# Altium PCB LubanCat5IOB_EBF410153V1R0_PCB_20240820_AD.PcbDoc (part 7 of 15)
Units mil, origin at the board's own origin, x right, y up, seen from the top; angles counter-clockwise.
Board outline 6811.02 x 4055.12 mil, 6 copper layers (TOP, GND02, ART03, ART04, PWR05, BOTTOM), stack 59.279 mil thick; 981 components, 783 nets, 3627 pads, 2669 vias.
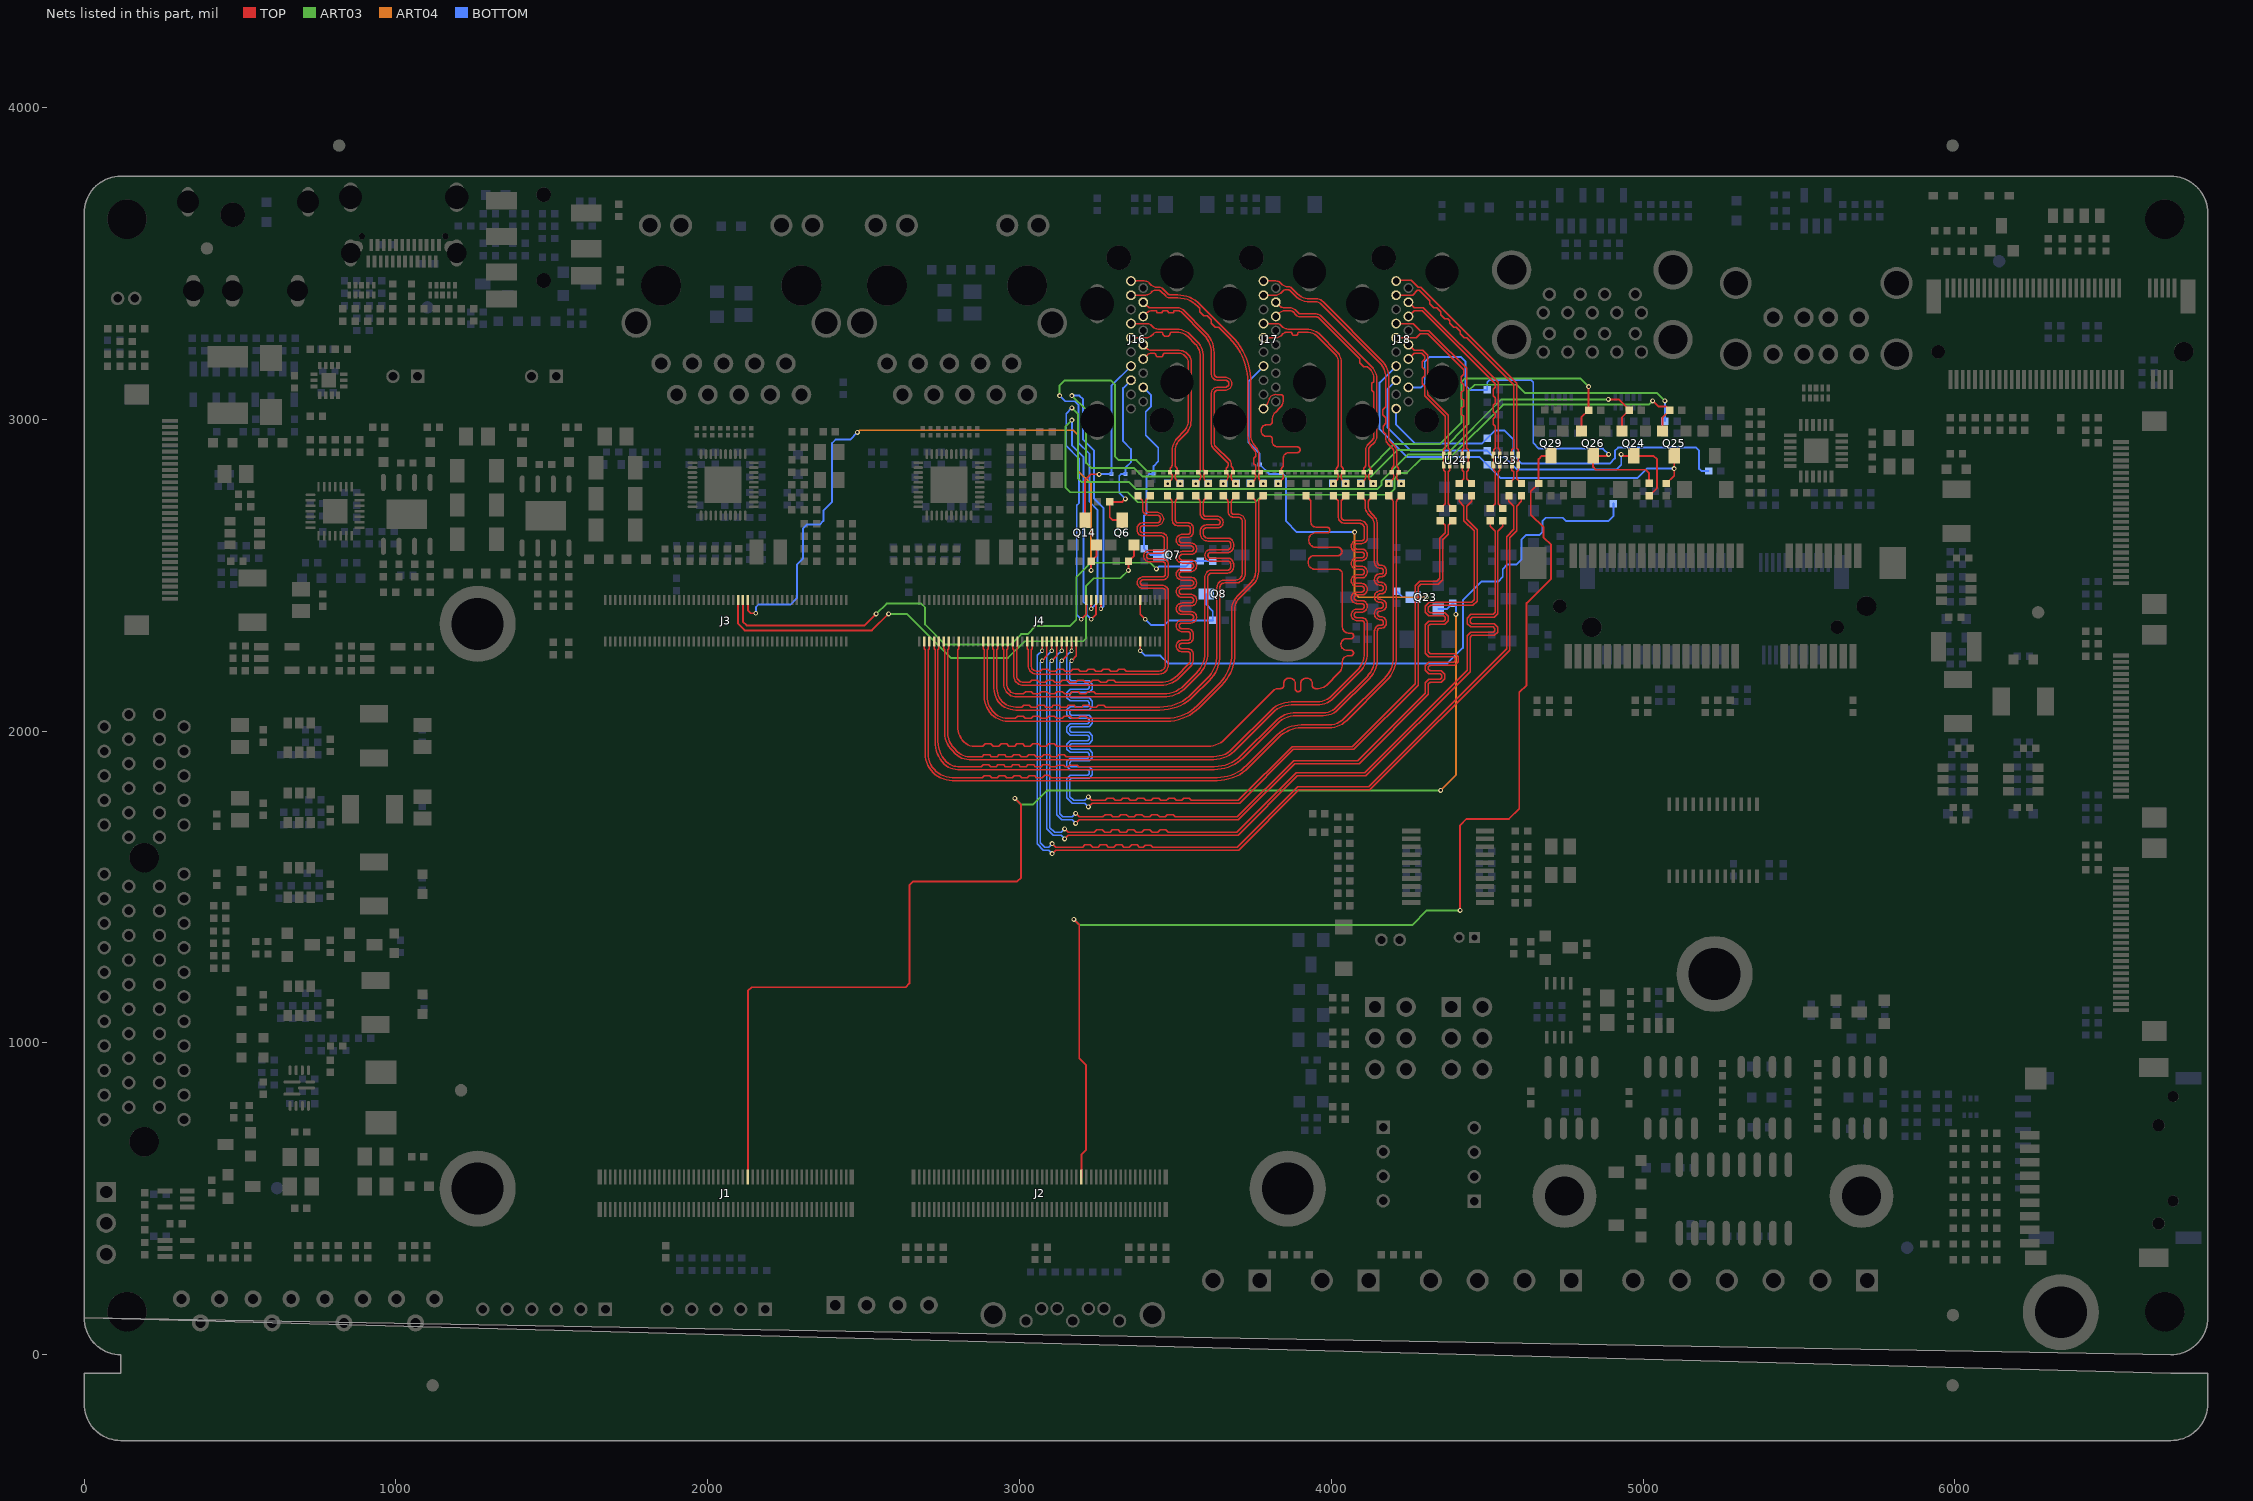
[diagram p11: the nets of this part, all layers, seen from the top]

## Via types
v1: diameter 16, hole 8, TOP to BOTTOM, 2357 vias
v2: diameter 14, hole 8, TOP to BOTTOM, 308 vias
v3: diameter 20, hole 10, TOP to BOTTOM, 4 vias

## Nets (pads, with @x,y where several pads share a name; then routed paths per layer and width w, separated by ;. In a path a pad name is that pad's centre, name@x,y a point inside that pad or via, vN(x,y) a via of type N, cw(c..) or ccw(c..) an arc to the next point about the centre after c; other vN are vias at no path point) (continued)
HDMI1_EARC-: C152.2 D34.2 J17.19 R180.2 | length 559.6
  TOP w4.5: J17.19@3782.91,3034.23 3784.53,3035.85 ccw(c3740.18,3080.21) 3800.54,3063.13 cw(c3822.28,3056.98) 3801,3064.57 3801,3064.73 cw(c3805.5,3064.72) 3801.75,3067.21 ccw(c3782.92,3079.7) 3802.43,3068.31 cw(c3821.95,3056.93) 3818.53,3079.26 ccw(c3815.03,3101.59) 3818.69,3079.29 cw(c3822.28,3056.98) 3825.87,3079.29 ccw(c3829.46,3101.6) 3829.46,3079 3837.5,3079 cw(c3837.5,3070) 3846.5,3070 3846.5,3063.8 cw(c3808.2,3063.8) 3835.28,3036.72 3821.77,3023.2 ccw(c3848.97,2996) 3810.5,2996 3810.5,2991.47 cw(c3801.5,2991.47) 3801.5,2982.47 3793.5,2982.47 ccw(c3793.5,2963.97) 3775,2963.97 3775,2963.22 ccw(c3792.75,2963.22) 3792.75,2945.47 3802.93,2945.47 cw(c3802.93,2937.9) 3810.5,2937.9 3810.5,2930.34 ccw(c3829.48,2930.34) 3829.48,2911.35 3891.5,2911.35 cw(c3891.5,2902.35) 3891.5,2893.35 3864.75,2893.35 ccw(c3864.75,2874.85) 3846.25,2874.85 3846.25,2852.6 cw(c3838.15,2852.6) 3843.88,2846.87 3842.72,2845.71 ccw(c3849.7,2838.73) 3839.83,2838.73 D34.2@3839.83,2830 3843.12,2826.71 cw(c3836.71,2820.3) 3845.77,2820.3 3845.77,2813.18 cw(c3837.67,2813.18) 3843.4,2807.45 v1(3830,2794.05)
HDMI1_TX_ON: J4.91 R190.1 | length 1971.7
  TOP w6: v2(3387.41,2258.14) J4.91@3387.41,2286.88
  BOTTOM w6: v2(3387.41,2258.14) 3403.55,2242 3452,2242 3477,2217 4372.63,2217 4422.2,2266.57 4422.2,2420.2 4481.37,2479.37 4535,2479.37 4550,2494.37 4550,2519.37 4565,2534.37 4595,2534.37 4610,2549.37 4610,2614.37 4625,2629.37 4668,2629.37 4678,2639.37 4678,2674.37 4688,2684.37 4743,2684.37 4754,2673.37 4889,2673.37 4905,2689.37 R190.1@4905,2729.69
HDMI_RX0N_PORT: J18.9 R206.2 U24.4 U24.7 | length 663.3
  TOP w4.5: J18.9@4208.11,3261.59 4208.46,3261.94 4272.31,3261.94 4284.75,3274.37 4309,3274.37 4324.75,3258.62 4324.9,3258.62 4424.5,3159.02 4424.5,3144.49 4417,3136.99 4417,3118.99 4424.5,3111.49 4424.5,3093.49 4417,3085.99 4417,3067.99 4424.5,3060.49 4424.5,3042.49 4417,3034.99 4417,3016.99 4424.5,3009.49 4424.5,2906.69 4419.69,2901.88 U24.7@4419.69,2885.12 U24.4@4419.69,2853.62 4419.69,2836.86 4424.78,2831.77 4424.78,2808.83 R206.2@4410,2794.05
HDMI_RX0P_PORT: J18.7 R205.2 U24.5 U24.6 | length 665.4
  TOP w4.5: J18.7@4208.11,3307.05 4208.19,3307.13 4262.24,3307.13 4285.5,3283.87 4312.94,3283.87 4328.69,3268.12 4328.84,3268.12 4434,3162.96 4434,2907.25 4439.37,2901.88 U24.6@4439.37,2885.12 U24.5@4439.37,2853.62 4439.37,2836.86 4434.28,2831.77 4434.28,2809.77 R205.2@4450,2794.05
HDMI_RX1N_PORT: J18.6 R204.2 U23.1 U23.10 | length 809.4
  TOP w4.5: J18.6@4247.48,3330.05 4265.48,3348.05 4291.88,3348.05 4525.5,3114.43 4525.5,3102.08 4519,3095.58 4519,3075.58 4525.5,3069.08 4525.5,3051.08 4519,3044.58 4519,3024.58 4525.5,3018.08 4525.5,3008.58 4519,3002.08 4519,2984.08 4525.5,2977.58 4525.5,2907.19 4520.63,2902.32 U23.10@4520.63,2885.12 U23.1@4520.63,2853.62 4520.63,2836.86 4525.72,2831.77 4525.72,2729.77 R204.2@4510,2714.05
HDMI_RX1P_PORT: J18.4 R203.2 U23.2 U23.9 | length 808.8
  TOP w4.5: J18.4@4247.48,3375.55 4265.48,3357.55 4295.82,3357.55 4535,3118.37 4535,2907.19 4540.31,2901.88 U23.9@4540.31,2885.12 U23.2@4540.31,2853.62 4540.31,2836.86 4535.22,2831.77 4535.22,2728.83 R203.2@4550,2714.05
HDMI_RX2N_PORT: J18.3 R202.2 U23.4 U23.7 | length 856.6
  TOP w4.5: J18.3@4208.11,3398 4208.27,3398.15 4260.78,3398.15 4275.99,3413.36 4282.57,3413.36 4315.23,3380.7 4315.23,3370.77 4327.96,3358.04 4337.89,3358.04 4350.62,3345.31 4350.62,3335.38 4363.35,3322.65 4373.28,3322.65 4380.01,3315.93 4380.01,3307.99 4392.73,3295.27 4400.67,3295.27 4413.4,3282.54 4413.4,3274.61 4426.12,3261.88 4434.06,3261.88 4584.78,3111.16 4584.78,2906.97 4579.69,2901.88 U23.7@4579.69,2885.12 U23.4@4579.69,2853.62 4579.69,2836.86 4584.78,2831.77 4584.78,2808.83 R202.2@4570,2794.05
HDMI_RX2P_PORT: J18.1 R201.2 U23.5 U23.6 | length 855.8
  TOP w4.5: J18.1@4208.11,3443.47 4210.01,3445.37 4256,3445.37 4278.51,3422.86 4286.51,3422.86 4594.28,3115.09 4594.28,2906.97 4599.37,2901.88 U23.6@4599.37,2885.12 U23.5@4599.37,2853.62 4599.37,2836.86 4594.28,2831.77 4594.28,2809.37 4609.6,2794.05 R201.2@4610,2794.05
HDMI_RX_CEC_M1: J4.74 Q25.2 R198.2 | length 3155.8
  TOP w6: v2(3229.93,2359) 3245.68,2374.75 J4.74@3245.68,2420.74 ; v1(5030.63,3059.37) 5048.63,3041.37 5073.32,3041.37 R198.2@5085.32,3029.37 5062.5,3006.55 Q25.2@5062.5,2962.87
  ART03 w6: v1(3168.02,2997.17) 3148,2977.15 3148,2781 3163,2766 3348,2766 3380,2734 3756,2734 3780,2758 4183,2758 4203,2778 4203,2811 4220,2828 4243,2828 4288,2873 4377,2873 4551,3047 5018.26,3047 v1(5030.63,3059.37)
  BOTTOM w6: v1(3168.02,2997.17) 3168.02,2916.98 3205,2880 3205,2415 3215.33,2404.67 3215.33,2373.6 v2(3229.93,2359)
HDMI_RX_CEC_PORT: D44.2 J18.13 Q25.3 R209.2 | length 1345.8
  TOP w6: R209.2@5075,2794.05 5100,2819.05 v1(5100,2841.77) Q25.3@5100,2882.87
  BOTTOM w6: J18.13@4208.11,3170.64 4155,3117.53 4155,2968 4244,2879 4475.69,2879 D44.2@4500.32,2854.37 4542.72,2811.97 4982.6,2811.97 5012.4,2841.77 v1(5100,2841.77)
HDMI_RX_CLKN: J4.65 R208.1 | length 3179.1
  TOP w4.5: v2(3166.94,2225.14) 3182.69,2240.89 J4.65@3182.69,2286.88 ; v1(3221,1788.83) 3231.33,1778.5 3275.58,1778.5 3278.83,1781.75 3282.08,1785 3300.08,1785 3303.32,1781.75 3306.57,1778.5 3324.57,1778.5 3327.82,1781.75 3331.07,1785 3349.07,1785 3352.32,1781.75 3355.57,1778.5 3373.57,1778.5 3376.82,1781.75 3380.07,1785 3398.07,1785 3401.32,1781.75 3404.57,1778.5 3422.57,1778.5 3425.82,1781.75 3429.06,1785 3447.06,1785 3450.31,1781.75 3453.56,1778.5 3471.56,1778.5 3474.81,1781.75 3478.06,1785 3496.06,1785 3499.31,1781.75 3502.56,1778.5 3520.56,1778.5 3523.81,1781.75 3527.06,1785 3545.06,1785 3548.3,1781.75 3551.55,1778.5 3702.5,1778.5 3874.5,1950.5 4068.06,1950.5 4269.28,2151.72 4269.28,2466.44 4283.85,2481 4338.56,2481 4347.5,2489.94 4347.5,2617.94 4365.25,2635.69 4365.25,2659.44 R208.1@4350,2674.69
  BOTTOM w4.5: v2(3166.94,2225.14) 3161,2219.2 3161,2166.41 3166.27,2161.14 3223.16,2161.14 3234,2150.3 3234,2134.98 3223.16,2124.14 3166.27,2124.14 3161,2118.87 3161,2111.41 3166.27,2106.14 3223.16,2106.14 3234,2095.3 3234,2079.98 3223.16,2069.14 3166.27,2069.14 3161,2063.87 3161,2056.41 3166.27,2051.14 3223.16,2051.14 3234,2040.31 3234,2024.98 3223.16,2014.14 3166.27,2014.14 3161,2008.87 3161,2001.41 3166.27,1996.14 3223.16,1996.14 3234,1985.31 3234,1969.98 3223.16,1959.14 3166.27,1959.14 3161,1953.87 3161,1946.41 3166.27,1941.14 3223.16,1941.14 3234,1930.31 3234,1914.98 3223.16,1904.14 3166.27,1904.14 3161,1898.87 3161,1891.41 3166.27,1886.14 3223.16,1886.14 3234,1875.31 3234,1859.98 3223.16,1849.14 3166.27,1849.14 3161,1843.87 3161,1790 3173.5,1777.5 3209.67,1777.5 v1(3221,1788.83)
HDMI_RX_CLKP: J4.63 R207.1 | length 3176.5
  TOP w4.5: v2(3166.94,2258.14) J4.63@3166.94,2286.88 ; v1(3221,1756.67) 3233.33,1769 3706.44,1769 3878.44,1941 4072,1941 4278.78,2147.78 4278.78,2462.5 4287.78,2471.5 4342.5,2471.5 4357,2486 4357,2614 4374.75,2631.75 4374.75,2659.44 R207.1@4390,2674.69
  BOTTOM w4.5: v2(3166.94,2258.14) 3151.5,2242.7 3151.5,2162.48 3162.34,2151.64 3219.23,2151.64 3224.5,2146.37 3224.5,2138.91 3219.23,2133.64 3162.34,2133.64 3151.5,2122.8 3151.5,2107.48 3162.34,2096.64 3219.23,2096.64 3224.5,2091.37 3224.5,2083.91 3219.23,2078.64 3162.34,2078.64 3151.5,2067.8 3151.5,2052.48 3162.34,2041.64 3219.23,2041.64 3224.5,2036.37 3224.5,2028.91 3219.23,2023.64 3162.34,2023.64 3151.5,2012.81 3151.5,1997.48 3162.34,1986.64 3219.23,1986.64 3224.5,1981.37 3224.5,1973.91 3219.23,1968.64 3162.34,1968.64 3151.5,1957.81 3151.5,1942.48 3162.34,1931.64 3219.23,1931.64 3224.5,1926.37 3224.5,1918.91 3219.23,1913.64 3162.34,1913.64 3151.5,1902.81 3151.5,1887.48 3162.34,1876.64 3219.23,1876.64 3224.5,1871.37 3224.5,1863.91 3219.23,1858.64 3162.34,1858.64 3151.5,1847.81 3151.5,1786.07 3169.57,1768 3209.67,1768 v1(3221,1756.67)
HDMI_RX_D0N: J4.61 R206.1 | length 3104
  TOP w4.5: v2(3135.44,2225.14) 3151.19,2240.89 J4.61@3151.19,2286.88 ; v1(3180,1736.33) 3191.33,1725 3267.73,1725 3274.73,1732 3292.73,1732 3299.73,1725 3317.73,1725 3324.73,1732 3342.73,1732 3349.73,1725 3367.73,1725 3374.73,1732 3392.73,1732 3399.73,1725 3417.73,1725 3424.73,1732 3442.73,1732 3449.73,1725 3467.73,1725 3474.73,1732 3492.73,1732 3499.73,1725 3698.56,1725 3879.06,1905.5 4085.5,1905.5 4302,2122 4302,2155.17 4312.84,2166.01 4349.23,2166.01 4354.5,2171.28 4354.5,2178.74 4349.23,2184.01 4312.84,2184.01 4302,2194.84 4302,2210.17 4312.84,2221.01 4392.23,2221.01 4397.5,2226.28 4397.5,2233.74 4392.23,2239.01 4312.84,2239.01 4302,2249.84 4302,2341.39 4312.84,2352.23 4360.23,2352.23 4365.5,2357.5 4365.5,2364.96 4360.23,2370.23 4312.84,2370.23 4302,2381.06 4302,2400.44 4314.56,2413 4450.56,2413 4458.5,2420.94 4458.5,2642.06 4425.25,2675.31 4425.25,2721.71 4410,2736.96 R206.1@4410,2754.69
  BOTTOM w4.5: v2(3135.44,2225.14) 3129.5,2219.2 3129.5,1734.94 3139.44,1725 3168.67,1725 v1(3180,1736.33)
HDMI_RX_D0P: J4.59 R205.1 | length 3103.9
  TOP w4.5: v2(3135.44,2258.14) J4.59@3135.44,2286.88 ; v1(3180,1704.17) 3191.33,1715.5 3702.5,1715.5 3883,1896 4089.44,1896 4311.5,2118.06 4311.5,2151.24 4316.77,2156.51 4353.16,2156.51 4364,2167.34 4364,2182.67 4353.16,2193.51 4316.77,2193.51 4311.5,2198.78 4311.5,2206.24 4316.77,2211.51 4396.16,2211.51 4407,2222.34 4407,2237.67 4396.16,2248.51 4316.77,2248.51 4311.5,2253.78 4311.5,2337.46 4316.77,2342.73 4364.16,2342.73 4375,2353.56 4375,2368.89 4364.16,2379.73 4316.77,2379.73 4311.5,2385 4311.5,2396.5 4318.5,2403.5 4454.5,2403.5 4468,2417 4468,2646 4434.75,2679.25 4434.75,2721.71 4450,2736.96 R205.1@4450,2754.69
  BOTTOM w4.5: v2(3135.44,2258.14) 3120,2242.7 3120,1731 3135.5,1715.5 3168.67,1715.5 v1(3180,1704.17)
HDMI_RX_D1N: J4.57 R204.1 | length 2928.6
  TOP w4.5: v2(3103.95,2225.14) 3119.7,2240.89 J4.57@3119.7,2286.88 ; v1(3145,1686.33) 3155.83,1675.5 3239.79,1675.5 3247.29,1683 3265.29,1683 3272.79,1675.5 3290.79,1675.5 3298.29,1683 3316.29,1683 3323.79,1675.5 3341.79,1675.5 3349.29,1683 3367.29,1683 3374.79,1675.5 3392.79,1675.5 3400.29,1683 3418.29,1683 3425.79,1675.5 3443.79,1675.5 3451.29,1683 3469.29,1683 3476.79,1675.5 3697.06,1675.5 3887.56,1866 4107,1866 4436,2195 4436,2305.39 4446.84,2316.23 4519.23,2316.23 4524.5,2321.5 4524.5,2328.96 4519.23,2334.23 4446.84,2334.23 4436,2345.06 4436,2362.44 4448.06,2374.5 4519.06,2374.5 4525.25,2380.69 4525.25,2641.71 4510,2656.96 R204.1@4510,2674.69
  BOTTOM w4.5: v2(3103.95,2225.14) 3097.5,2218.7 3097.5,1690.5 3113,1675 3133.67,1675 v1(3145,1686.33)
HDMI_RX_D1P: J4.55 R203.1 | length 2926.9
  TOP w4.5: v2(3103.95,2258.14) J4.55@3103.95,2286.88 ; v1(3145,1654.17) 3156.83,1666 3701,1666 3891.5,1856.5 4110.94,1856.5 4445.5,2191.06 4445.5,2301.46 4450.77,2306.73 4523.16,2306.73 4534,2317.56 4534,2332.89 4523.16,2343.73 4450.77,2343.73 4445.5,2349 4445.5,2358.5 4452,2365 4523,2365 4534.75,2376.75 4534.75,2641.71 4550,2656.96 R203.1@4550,2674.69
  BOTTOM w4.5: v2(3103.95,2258.14) 3088,2242.2 3088,1686.56 3109.07,1665.5 3133.67,1665.5 v1(3145,1654.17)
HDMI_RX_D2N: J4.53 R202.1 | length 2962.7
  TOP w4.5: v2(3072.45,2225.14) 3088.2,2240.89 J4.53@3088.2,2286.88 ; v1(3105,1639.33) 3116.33,1628 3202.75,1628 3209.75,1635 3227.75,1635 3234.75,1628 3252.75,1628 3259.75,1635 3277.75,1635 3284.75,1628 3302.75,1628 3309.75,1635 3327.75,1635 3334.75,1628 3352.75,1628 3359.75,1635 3377.75,1635 3384.75,1628 3396.81,1628 3402.81,1634 3420.81,1634 3426.81,1628 3699,1628 3892,1821 4119.56,1821 4562.5,2263.94 4562.5,2623.94 4585.25,2646.69 4585.25,2721.71 4570,2736.96 R202.1@4570,2754.69
  BOTTOM w4.5: v2(3072.45,2225.14) 3066.7,2219.39 3066.7,1642.24 3080.94,1628 3093.67,1628 v1(3105,1639.33)
HDMI_RX_D2P: J4.51 R201.1 | length 2963.4
  TOP w4.5: v2(3072.45,2258.14) J4.51@3072.45,2286.88 ; v1(3105,1607.17) 3116.33,1618.5 3702.94,1618.5 3895.94,1811.5 4123.5,1811.5 4572,2260 4572,2620 4594.75,2642.75 4594.75,2721.71 4610,2736.96 R201.1@4610,2754.69
  BOTTOM w4.5: v2(3072.45,2258.14) 3057.2,2242.89 3057.2,1638.3 3077.01,1618.5 3093.67,1618.5 v1(3105,1607.17)
HDMI_RX_DET: J2.67 Q29.3 R210.2 | length 3843.2
  TOP w6: v1(3174.81,1396) 3191.81,1379 3191.81,951 3213,929.81 3213,656 3198.43,641.43 J2.67@3198.43,569.96 ; v1(4413,1425) 4413,1698 4433,1718 4570,1718 4603,1751 4603,2124.37 4626.4,2147.77 4626.4,2410.6 4705,2489.2 4705,2597 4681.19,2620.82 4681.19,2653.18 4640,2694.37 4640,2769.05 R210.2@4665,2794.05 4665,2872.37 4675.5,2882.87 Q29.3@4705,2882.87
  ART03 w6: v1(3174.81,1396) 3192.81,1378 4260,1378 4307,1425 v1(4413,1425)
HDMI_RX_HPD_PORT: D41.2 J18.19 R214.2 | length 1270.8
  BOTTOM w6: J18.19@4208.11,3034.23 4208.11,2982.89 4269,2922 4482.95,2922 D41.2@4500.32,2939.37 4525.32,2964.37 4555,2964.37 4585,2934.37 4585,2884.37 4611.37,2858 4893.63,2858 4910,2874.37 4910,2899.37 4920,2909.37 5170,2909.37 5180,2899.37 5180,2841.17 5186.8,2834.37 R214.2@5210.32,2834.37
HDMI_RX_HPDOUT_M1: J4.76 R212.1 | length 3152.7
  TOP w6: v2(3261.43,2392) J4.76@3261.43,2420.74
  ART03 w6: v1(3168.02,3075.91) 3214,3029.93 3214,2860 3230,2844 3367,2844 3395,2816 4127,2816 4212,2901 4356,2901 4440,2985 4440,3091 4460,3111 4595,3111 4622,3084 5045.37,3084 v1(5070,3059.37)
  BOTTOM w6: v1(3168.02,3075.91) 3192.09,3075.91 3204,3064 3204,2935 3238.63,2900.37 3238.63,2746.37 3270,2715 3270,2400.57 v2(3261.43,2392) ; R212.1@5070,2994.05 v1(5070,3059.37)
HDMI_RX_SCL_M1: J4.70 Q24.2 R196.2 | length 3012.3
  TOP w6: v2(3198.43,2359) 3214.18,2374.75 J4.70@3214.18,2420.74 ; v1(4889,3064) 4921.37,3064 4955.32,3030.05 R196.2@4955.32,3029.37 4932.5,3006.55 Q24.2@4932.5,2962.87
  ART03 w6: v1(3168.02,3036.54) 3188,3016.56 3188,2810 3198.63,2799.37 3350.63,2799.37 3373,2777 4149,2777 4161,2789 4161,2802 4246,2887 4369,2887 4546,3064 v1(4889,3064)
  BOTTOM w6: v1(3168.02,3036.54) 3150,3018.52 3150,2915.2 3191,2874.2 3191,2731 3183.84,2723.84 3183.84,2373.6 v2(3198.43,2359)
HDMI_RX_SDA_M1: J4.72 Q26.2 R199.2 | length 3142.6
  TOP w6: v2(3229.93,2392) J4.72@3229.93,2420.74 ; Q26.2@4802.5,2962.87 4802.5,3006.55 R199.2@4825.32,3029.37 v1(4825.32,3105)
  ART03 w6: v1(3128.65,3075.91) 3128.65,3108.65 3145,3125 3293,3125 3306,3112 3306,2881 3318,2869 3375,2869 3410,2834 4115,2834 4202,2921 4349,2921 4418,2990 4418,3120 4429,3131 4799.32,3131 v1(4825.32,3105)
  BOTTOM w6: v1(3128.65,3075.91) 3146.56,3058 3177,3058 3189,3046 3189,2925 3224.63,2889.37 3224.63,2735.37 3250,2710 3250,2412.07 v2(3229.93,2392)
HDMI_RXCLKN_PORT: J18.12 R208.2 U24.1 U24.10 | length 602.9
  TOP w4.5: J18.12@4247.48,3193.52 4265.49,3211.52 4290.21,3211.52 4300,3201.74 4300,3192.24 4292,3184.24 4292,3166.24 4300,3158.24 4300,3140.24 4292,3132.24 4292,3114.24 4300,3106.24 4300,3074.9 4365.72,3009.18 4365.72,2906.97 4360.63,2901.88 U24.10@4360.63,2885.12 U24.1@4360.63,2853.62 4360.63,2836.86 4365.72,2831.77 4365.72,2729.77 R208.2@4350,2714.05
HDMI_RXCLKP_PORT: J18.10 R207.2 U24.2 U24.9 | length 605
  TOP w4.5: J18.10@4247.48,3239.03 4265.48,3221.02 4294.15,3221.02 4309.5,3205.67 4309.5,3078.84 4375.22,3013.12 4375.22,2906.97 4380.31,2901.88 U24.9@4380.31,2885.12 U24.2@4380.31,2853.62 4380.31,2836.86 4375.22,2831.77 4375.22,2728.83 R207.2@4390,2714.05
HDMI_RXDDC_SCL_PORT: D43.2 J18.15 Q24.3 R197.2 | length 1257.1
  TOP w6: v1(4930,2887.5) 4934.63,2882.87 Q24.3@4970,2882.87 5033.5,2882.87 5045,2871.37 5045,2779.69 R197.2@5019.68,2754.37
  BOTTOM w6: J18.15@4208.11,3125.16 4180,3097.05 4180,2974 4254.63,2899.37 D43.2@4500.32,2899.37 4521.52,2878.17 4556.2,2878.17 4595,2839.37 4915,2839.37 4930,2854.37 v1(4930,2887.5)
HDMI_RXDDC_SDA_PORT: D42.2 J18.16 Q26.3 R200.2 | length 1359.8
  TOP w6: v1(4890,2887.5) 4885.37,2882.87 Q26.3@4840,2882.87 4840,2847.37 4849,2838.37 5008,2838.37 5019.68,2826.69 R200.2@5019.68,2794.37
  BOTTOM w6: J18.16@4247.48,3102.49 4288.2,3102.49 4300,3114.29 4300,3184.37 4315,3199.37 4416.2,3199.37 4431,3184.57 4431,3108.37 4445,3094.37 D42.2@4500.32,3094.37 4500.32,3118.37 4508.32,3126.37 4640.03,3126.37 4648.03,3118.37 4648.03,2924.23 4666.2,2906.06 4871.44,2906.06 v1(4890,2887.5)
HDMI_TX0_CEC_M0: J3.60 Q14.2 R170.2 | length 2146
  TOP w6: J3.60@2128.84,2420.74 2128.84,2388 2138.84,2378 v2(2154.52,2378) ; v1(3229.68,2515.68) R170.2@3229.68,2545 3247.5,2562.82 Q14.2@3247.5,2596.5
  ART04 w6: v1(2480.1,2957.8) 2487.3,2965 3172.7,2965 3187,2950.7 3187,2835.71 3229.68,2793.03 v1(3229.68,2515.68)
  BOTTOM w6: v2(2154.52,2378) 2154.52,2397.52 2163,2406 2266,2406 2286,2426 2286,2534 2306,2554 2306,2650 2318,2662 2359,2662 2371,2674 2371,2707 2399,2735 2399,2924 2410,2935 2457.3,2935 v1(2480.1,2957.8)
HDMI_TX0_CEC_PORT: D31.2 J16.13 Q14.3 | length 593.7
  TOP w6: Q14.3@3210,2676.5 3210,2805 3228.74,2823.74 v1(3255.63,2823.74)
  BOTTOM w6: v1(3255.63,2823.74) 3256.45,2824.56 D31.2@3295,2824.56 3295,3107.92 J16.13@3357.72,3170.64
HDMI_TX0_D0N: C136.1 J4.37 | length 1792.2
  TOP w4.5: J4.37@2962.22,2286.88 2962.22,2263.82 2959.09,2260.7 2959.09,2151.89 ccw(c2991.98,2151.89) 2991.98,2119 3012.9,2119 3019.9,2126 3037.9,2126 3044.9,2119 3062.9,2119 3069.9,2126 3087.9,2126 3094.9,2119 3112.9,2119 3119.9,2126 3137.9,2126 3144.9,2119 3162.9,2119 3169.9,2126 3187.9,2126 3194.9,2119 3212.9,2119 3219.9,2126 3237.9,2126 3244.9,2119 3461.54,2119 ccw(c3461.54,2213.2) 3528.16,2146.59 3567.26,2185.7 ccw(c3501.51,2251.45) 3594.5,2251.45 3594.5,2492.74 cw(c3618.26,2492.74) 3618.26,2516.5 3668,2516.5 ccw(c3668,2525.5) 3677,2525.5 3677,2536 ccw(c3668,2536) 3668,2545 3613.5,2545 cw(c3613.5,2563.5) 3613.5,2582 3668,2582 ccw(c3668,2591) 3677,2591 3677,2600.5 ccw(c3668,2600.5) 3668,2609.5 3603.77,2609.5 cw(c3603.77,2633.02) 3580.25,2633.02 3580.25,2642.52 cw(c3598.75,2642.52) 3598.75,2661.02 3634.5,2661.02 ccw(c3634.5,2670.02) 3634.5,2679.02 3598.75,2679.02 cw(c3598.75,2697.52) 3580.25,2697.52 3580.25,2733 ccw(c3564.7,2733) 3575.7,2743.99 C136.1@3565,2754.69
HDMI_TX0_D0N_PORT: C136.2 D50.2 J16.9 R167.1 | length 703.3
  TOP w4.5: J16.9@3357.72,3261.59 3374.49,3261.59 3374.53,3261.62 3407.43,3261.62 ; 3407.43,3261.63 ccw(c3407.43,3284.13) 3423.35,3268.22 3428.41,3273.28 cw(c3444.32,3257.37) 3444.32,3279.87 3453.82,3279.87 cw(c3453.82,3273.43) 3460.26,3273.43 ccw(c3466.69,3273.43) 3466.69,3267 3476.32,3267 ccw(c3476.32,3273.43) 3482.76,3273.43 cw(c3489.19,3273.43) 3489.19,3279.87 3504.52,3279.87 cw(c3504.52,3228.75) 3540.67,3264.9 3562.69,3242.88 ; 3562.69,3242.87 cw(c3519.69,3199.88) 3580.5,3199.88 3580.5,2840.94 cw(c3570.2,2840.94) 3577.48,2833.65 D50.2@3573.83,2830 3577.98,2825.85 cw(c3569.49,2817.36) 3581.5,2817.36 3581.5,2815.99 cw(c3568.37,2815.99) 3577.65,2806.7 v1(3565,2794.05)
HDMI_TX0_D0P: C135.1 J4.35 | length 1793.1
  TOP w4.5: J4.35@2946.47,2286.88 2946.47,2263.82 2949.59,2260.7 2949.59,2151.89 ccw(c2991.98,2151.89) 2991.98,2109.5 3461.54,2109.5 ccw(c3461.54,2213.2) 3534.87,2139.87 3573.98,2178.98 ccw(c3501.51,2251.45) 3604,2251.45 3604,2492.74 cw(c3618.26,2492.74) 3618.26,2507 3668,2507 ccw(c3668,2525.5) 3686.5,2525.5 3686.5,2536 ccw(c3668,2536) 3668,2554.5 3613.5,2554.5 cw(c3613.5,2563.5) 3613.5,2572.5 3668,2572.5 ccw(c3668,2591) 3686.5,2591 3686.5,2600.5 ccw(c3668,2600.5) 3668,2619 3603.77,2619 cw(c3603.77,2633.02) 3589.75,2633.02 3589.75,2642.52 cw(c3598.75,2642.52) 3598.75,2651.52 3634.5,2651.52 ccw(c3634.5,2670.02) 3634.5,2688.52 3598.75,2688.52 cw(c3598.75,2697.52) 3589.75,2697.52 3589.75,2733 cw(c3605.3,2733) 3594.3,2743.99 C135.1@3605,2754.69
HDMI_TX0_D0P_PORT: C135.2 D51.2 J16.7 R168.1 | length 701.7
  TOP w4.5: J16.7@3357.72,3307.05 3374.49,3307.05 3374.57,3307.13 3407.92,3307.13 cw(c3407.92,3284.63) 3423.83,3300.54 3428.41,3295.96 ccw(c3444.32,3311.87) 3444.32,3289.37 3504.52,3289.37 cw(c3504.52,3228.75) 3547.38,3271.62 3569.41,3249.59 cw(c3519.69,3199.88) 3590,3199.88 3590,2841.79 ccw(c3601.15,2841.79) 3593.27,2833.9 D51.2@3597.17,2830 3593.77,2826.6 ccw(c3600.45,2819.92) 3591,2819.92 3591,2815.49 ccw(c3608.96,2815.49) 3596.26,2802.79 v1(3605,2794.05)
HDMI_TX0_D1N: C134.1 J4.33 | length 1614.6
  TOP w4.5: J4.33@2930.72,2286.88 2930.72,2263.82 2927.59,2260.7 2927.59,2137.35 ccw(c2987.94,2137.35) 2945.27,2094.68 ccw(c2987.94,2137.34) 2987.94,2077 3007.03,2077 3013.03,2083 3031.03,2083 3037.03,2077 3055.03,2077 3061.03,2083 3079.03,2083 3085.03,2077 3103.03,2077 3109.03,2083 3127.03,2083 3133.03,2077 3151.03,2077 3157.03,2083 3175.03,2083 3181.03,2077 3199.03,2077 3205.03,2083 3223.03,2083 3229.03,2077 3247.03,2077 3253.03,2083 3271.03,2083 3277.03,2077 3450.71,2077 ccw(c3450.71,2221.51) 3552.89,2119.33 3601.33,2167.76 ccw(c3523.65,2245.44) 3633.5,2245.43 3633.5,2460.26 cw(c3657.74,2460.26) 3657.74,2484.5 3693.31,2484.5 ccw(c3693.31,2505.69) 3714.5,2505.69 3714.5,2672.74 ccw(c3701.49,2672.74) 3701.49,2685.75 3687.75,2685.75 cw(c3687.75,2704.25) 3669.25,2704.25 3669.25,2733 ccw(c3653.7,2733) 3664.7,2743.99 C134.1@3654,2754.69
HDMI_TX0_D1N_PORT: C134.2 D52.2 J16.6 R165.1 | length 847.7
  TOP w4.5: J16.6@3397.09,3330.05 3408.98,3341.94 cw(c3423.73,3327.2) 3423.73,3348.05 3437.07,3348.05 cw(c3437.07,3344.53) 3440.59,3344.53 ; 3440.59,3344.53 ccw(c3444.12,3344.53) 3444.12,3341 3455.07,3341 ccw(c3455.07,3344.53) 3458.59,3344.53 ; 3458.59,3344.53 cw(c3462.12,3344.53) 3462.12,3348.05 3473.07,3348.05 cw(c3473.07,3344.53) 3476.59,3344.53 ; 3476.59,3344.53 ccw(c3480.12,3344.53) 3480.12,3341 3491.07,3341 ccw(c3491.07,3344.53) 3494.59,3344.53 ; 3494.59,3344.53 cw(c3498.12,3344.53) 3498.12,3348.05 3508.93,3348.05 cw(c3508.93,3335.05) 3518.13,3344.24 3590.97,3271.4 cw(c3532.96,3213.39) 3615,3213.39 3615,3146.12 ccw(c3635.75,3146.12) 3635.75,3125.37 3660.25,3125.37 cw(c3660.25,3114.12) 3660.25,3102.87 3635.75,3102.87 ccw(c3635.75,3082.12) 3615,3082.12 3615,2923.32 ccw(c3637.5,2923.32) 3621.59,2907.41 3667.12,2861.88 cw(c3661.99,2856.74) 3669.25,2856.74 3669.25,2853.33 cw(c3659.38,2853.33) 3666.36,2846.35 3665.72,2845.71 ccw(c3672.7,2838.73) 3662.83,2838.73 D52.2@3662.83,2830 3666.23,2826.6 cw(c3659.55,2819.92) 3669,2819.92 3669,2815.99 cw(c3652.24,2815.99) 3664.09,2804.14 v1(3654,2794.05)
HDMI_TX0_D1P: C133.1 J4.31 | length 1614.6
  TOP w4.5: J4.31@2914.97,2286.88 2914.97,2263.82 2918.09,2260.7 2918.09,2137.35 ccw(c2987.94,2137.35) 2938.55,2087.96 ccw(c2987.94,2137.34) 2987.94,2067.5 3450.71,2067.5 ccw(c3450.71,2221.51) 3559.61,2112.61 3608.04,2161.04 ccw(c3523.65,2245.43) 3643,2245.43 3643,2460.26 cw(c3657.74,2460.26) 3657.74,2475 3693.31,2475 ccw(c3693.31,2505.69) 3724,2505.69 3724,2672.74 ccw(c3701.49,2672.74) 3701.49,2695.25 3687.75,2695.25 cw(c3687.75,2704.25) 3678.75,2704.25 3678.75,2733 cw(c3694.3,2733) 3683.3,2743.99 C133.1@3694,2754.69
HDMI_TX0_D1P_PORT: C133.2 D53.2 J16.4 R166.1 | length 847.1
  TOP w4.5: J16.4@3397.09,3375.55 3410.41,3362.24 ccw(c3421.71,3373.54) 3421.71,3357.55 3508.93,3357.55 cw(c3508.93,3335.05) 3524.85,3350.96 3597.69,3278.12 cw(c3532.95,3213.39) 3624.5,3213.39 3624.5,3146.12 ccw(c3635.75,3146.12) 3635.75,3134.87 3660.25,3134.87 cw(c3660.25,3114.12) 3660.25,3093.37 3635.75,3093.37 ccw(c3635.75,3082.12) 3624.5,3082.12 3624.5,2923.32 ccw(c3637.5,2923.32) 3628.31,2914.13 3673.84,2868.59 cw(c3661.99,2856.74) 3678.75,2856.74 3678.75,2853.33 ccw(c3688.62,2853.33) 3681.64,2846.35 3682.28,2845.71 cw(c3675.3,2838.73) 3685.17,2838.73 D53.2@3685.17,2830 3681.52,2826.35 ccw(c3688.8,2819.06) 3678.5,2819.06 3678.5,2815.99 ccw(c3694.05,2815.99) 3683.05,2805 v1(3694,2794.05)
HDMI_TX0_D2N: C132.1 J4.29 | length 1677.1
  TOP w4.5: J4.29@2899.22,2286.88 2899.22,2263.82 2896.1,2260.7 2896.1,2112.28 ccw(c2970.38,2112.28) 2917.86,2059.76 ccw(c2963.14,2105.04) 2963.14,2041 2987.22,2041 2994.22,2048 3012.22,2048 3019.22,2041 3037.22,2041 3044.22,2048 3062.22,2048 3069.22,2041 3087.22,2041 3094.22,2048 3112.22,2048 3119.22,2041 3137.22,2041 3144.22,2048 3162.22,2048 3169.22,2041 3187.22,2041 3194.22,2048 3212.22,2048 3219.22,2041 3471.72,2041 ccw(c3471.72,2179.29) 3569.51,2081.51 3642.04,2154.04 ccw(c3547.98,2248.1) 3681,2248.1 3681,2390.83 cw(c3739.35,2390.83) 3698.09,2432.09 3742.92,2476.92 ccw(c3708.31,2511.52) 3757.25,2511.52 3757.25,2734 ccw(c3744.12,2734) 3753.4,2743.29 C132.1@3742,2754.69
HDMI_TX0_D2N_PORT: C132.2 D54.2 J16.3 R163.1 | length 896.9
  TOP w4.5: J16.3@3357.72,3398 3374.49,3398 3374.97,3398.48 3404.79,3398.48 ccw(c3404.79,3420.98) 3420.7,3405.07 3423.41,3407.78 cw(c3439.32,3391.87) 3439.32,3414.37 3444.61,3414.37 cw(c3444.61,3401.37) 3453.81,3410.56 3468.41,3395.96 ccw(c3484.32,3411.87) 3484.32,3389.37 3507.54,3389.37 cw(c3507.54,3298.46) 3571.82,3362.74 3578.54,3356.02 3578.54,3344.46 3591.27,3331.73 3602.83,3331.73 3615.56,3319 3615.56,3307.44 3628.29,3294.71 3639.85,3294.71 3673.26,3261.3 cw(c3530.25,3118.29) 3732.5,3118.29 3732.5,2950.28 ccw(c3800.04,2950.28) 3752.28,2902.52 3753.38,2901.43 cw(c3742.82,2890.88) 3757.75,2890.88 3757.75,2881.38 3752,2875.63 3752,2857.63 3757.75,2851.88 3757.75,2841.36 cw(c3747.02,2841.36) 3754.61,2833.78 D54.2@3750.83,2830 3754.37,2826.46 cw(c3747.36,2819.45) 3757.27,2819.45 3757.27,2815.99 cw(c3741.18,2815.99) 3752.56,2804.61 v1(3742,2794.05)
HDMI_TX0_D2P: C131.1 J4.27 | length 1677.9
  TOP w4.5: J4.27@2883.47,2286.88 2883.47,2263.82 2886.6,2260.7 2886.6,2112.28 ccw(c2970.38,2112.28) 2911.14,2053.04 ccw(c2963.13,2105.04) 2963.13,2031.5 3471.72,2031.5 ccw(c3471.72,2179.29) 3576.22,2074.79 3648.76,2147.32 ccw(c3547.98,2248.1) 3690.5,2248.1 3690.5,2390.83 cw(c3739.35,2390.83) 3704.81,2425.37 3749.63,2470.2 ccw(c3708.31,2511.52) 3766.75,2511.52 3766.75,2734 cw(c3779.88,2734) 3770.6,2743.29 C131.1@3782,2754.69
HDMI_TX0_D2P_PORT: C131.2 D65.2 J16.1 R164.1 | length 895.4
  TOP w4.5: J16.1@3357.72,3443.47 3374.49,3443.47 3374.7,3443.68 3400.87,3443.68 cw(c3400.87,3421.18) 3416.78,3437.09 3423.41,3430.46 ccw(c3439.32,3446.37) 3439.32,3423.87 3444.61,3423.87 cw(c3444.62,3401.37) 3460.53,3417.28 3475.13,3402.68 ccw(c3484.32,3411.87) 3484.32,3398.87 3507.54,3398.87 cw(c3507.54,3298.46) 3578.54,3369.46 3679.98,3268.02 cw(c3530.25,3118.29) 3742,3118.29 3742,2950.28 ccw(c3800.04,2950.28) 3759,2909.24 3759.55,2908.7 3760.09,2908.16 cw(c3742.82,2890.88) 3767.25,2890.88 3767.25,2841.36 ccw(c3777.98,2841.36) 3770.39,2833.78 D65.2@3774.17,2830 3770.15,2825.98 ccw(c3778.32,2817.82) 3766.77,2817.82 3766.77,2815.49 ccw(c3781.77,2815.49) 3771.17,2804.88 v1(3782,2794.05)
HDMI_TX0_D3N: C138.1 J4.41 | length 1892.4
  TOP w4.5: J4.41@2993.71,2286.88 2993.71,2263.82 2990.59,2260.7 2990.59,2178.78 ccw(c3012.87,2178.78) 3012.87,2156.5 3032.95,2156.5 3039.45,2163 3057.45,2163 3063.95,2156.5 3081.95,2156.5 3088.45,2163 3106.45,2163 3112.95,2156.5 3130.95,2156.5 3137.45,2163 3155.45,2163 3161.95,2156.5 3179.95,2156.5 3186.45,2163 3204.45,2163 3210.95,2156.5 3228.95,2156.5 3235.45,2163 3253.45,2163 3259.95,2156.5 3277.95,2156.5 3284.45,2163 3302.45,2163 3308.95,2156.5 3453.63,2156.5 ccw(c3453.63,2229.97) 3505.58,2178.02 3541.88,2214.31 ccw(c3525.89,2230.3) 3548.5,2230.3 3548.5,2245.5 ccw(c3539.5,2245.5) 3539.5,2254.5 3521.5,2254.5 cw(c3521.5,2273) 3521.5,2291.5 3539.5,2291.5 ccw(c3539.5,2300.5) 3548.5,2300.5 3548.5,2310 ccw(c3539.5,2310) 3539.5,2319 3521.5,2319 cw(c3521.5,2337.5) 3521.5,2356 3549.5,2356 ccw(c3549.5,2365) 3549.5,2374 3521.5,2374 cw(c3521.5,2392.5) 3521.5,2411 3549.5,2411 ccw(c3549.5,2420) 3549.5,2429 3521.5,2429 cw(c3521.5,2447.5) 3521.5,2466 3549.5,2466 ccw(c3549.5,2475) 3549.5,2484 3521.5,2484 cw(c3521.5,2502.5) 3521.5,2521 3549.5,2521 ccw(c3549.5,2530) 3549.5,2539 3521.5,2539 cw(c3521.5,2557.5) 3521.5,2576 3549.5,2576 ccw(c3549.5,2585) 3549.5,2594 3521.5,2594 cw(c3521.5,2612.5) 3521.5,2631 3539.5,2631 ccw(c3539.5,2640) 3548.5,2640 3548.5,2649.5 ccw(c3539.5,2649.5) 3539.5,2658.5 3508.75,2658.5 cw(c3508.75,2677) 3490.25,2677 3490.25,2732 ccw(c3472.29,2732) 3484.99,2744.7 C138.1@3475,2754.69
HDMI_TX0_D3N_PORT: C138.2 D5.2 J16.12 R161.1 | length 595.2
  TOP w4.5: J16.12@3397.09,3193.52 3409.78,3206.21 cw(c3422.6,3193.4) 3422.6,3211.52 3432.1,3211.52 cw(c3432.1,3205.76) 3437.86,3205.76 ccw(c3443.62,3205.76) 3443.62,3200 3454.6,3200 ccw(c3454.6,3205.76) 3460.36,3205.76 cw(c3466.12,3205.76) 3466.12,3211.52 3513.03,3211.52 cw(c3513.03,3187.34) 3530.13,3204.44 3534.08,3200.48 cw(c3516.98,3183.39) 3541.16,3183.39 3541.16,2996.42 cw(c3489.36,2996.42) 3525.99,2959.8 3507.13,2940.93 ccw(c3549.08,2898.98) 3489.75,2898.98 3489.75,2854.19 cw(c3479.02,2854.19) 3486.61,2846.6 3485.97,2845.96 ccw(c3493.56,2838.38) 3482.83,2838.38 D5.2@3482.83,2830 3486.73,2826.1 cw(c3478.85,2818.21) 3490,2818.21 3490,2815.49 cw(c3474.45,2815.49) 3485.45,2804.5 v1(3475,2794.05)
HDMI_TX0_D3P: C137.1 J4.39 | length 1889.9
  TOP w4.5: J4.39@2977.96,2286.88 2977.96,2263.82 2981.09,2260.7 2981.09,2178.78 ccw(c3012.87,2178.78) 3012.87,2147 3453.63,2147 ccw(c3453.63,2229.97) 3512.3,2171.3 3548.6,2207.6 ccw(c3525.89,2230.3) 3558,2230.3 3558,2245.5 ccw(c3539.5,2245.5) 3539.5,2264 3521.5,2264 cw(c3521.5,2273) 3521.5,2282 3539.5,2282 ccw(c3539.5,2300.5) 3558,2300.5 3558,2310 ccw(c3539.5,2310) 3539.5,2328.5 3521.5,2328.5 cw(c3521.5,2337.5) 3521.5,2346.5 3549.5,2346.5 ccw(c3549.5,2365) 3549.5,2383.5 3521.5,2383.5 cw(c3521.5,2392.5) 3521.5,2401.5 3549.5,2401.5 ccw(c3549.5,2420) 3549.5,2438.5 3521.5,2438.5 cw(c3521.5,2447.5) 3521.5,2456.5 3549.5,2456.5 ccw(c3549.5,2475) 3549.5,2493.5 3521.5,2493.5 cw(c3521.5,2502.5) 3521.5,2511.5 3549.5,2511.5 ccw(c3549.5,2530) 3549.5,2548.5 3521.5,2548.5 cw(c3521.5,2557.5) 3521.5,2566.5 3549.5,2566.5 ccw(c3549.5,2585) 3549.5,2603.5 3521.5,2603.5 cw(c3521.5,2612.5) 3521.5,2621.5 3539.5,2621.5 ccw(c3539.5,2640) 3558,2640 3558,2649.5 ccw(c3539.5,2649.5) 3539.5,2668 3508.75,2668 cw(c3508.75,2677) 3499.75,2677 3499.75,2732 cw(c3517.71,2732) 3505.01,2744.7 C137.1@3515,2754.69
HDMI_TX0_D3P_PORT: C137.2 D14.2 J16.10 R162.1 | length 596.8
  TOP w4.5: J16.10@3397.09,3239.03 3408.5,3227.61 ccw(c3424.41,3243.52) 3424.41,3221.02 3513.03,3221.02 cw(c3513.03,3187.34) 3536.84,3211.16 3540.8,3207.2 cw(c3516.98,3183.39) 3550.66,3183.39 3550.66,2996.42 cw(c3489.36,2996.42) 3532.71,2953.08 3513.85,2934.22 ccw(c3549.08,2898.98) 3499.25,2898.98 3499.25,2854.19 ccw(c3509.98,2854.19) 3502.39,2846.6 3503.03,2845.96 cw(c3495.44,2838.38) 3506.17,2838.38 D14.2@3506.17,2830 3502.52,2826.35 ccw(c3509.8,2819.06) 3499.5,2819.06 3499.5,2815.99 ccw(c3515.05,2815.99) 3504.05,2805 v1(3515,2794.05)
HDMI_TX0_HPD_M0: J4.92 Q8.3 R157.2 | length 393.5
  TOP w6: J4.92@3387.41,2420.74 3387.41,2374.75 v2(3403.16,2359)
  BOTTOM w6: v2(3403.16,2359) 3422.16,2340 3465,2340 3480,2355 R157.2@3620.32,2355 3620,2355.32 3620,2385 3598.5,2406.5 Q8.3@3598.5,2440
HDMI_TX0_SBDN: C140.1 J4.47 | length 1561.2
  TOP w4.5: J4.47@3040.95,2286.88 3040.95,2263.82 3037.83,2260.7 3037.83,2208.88 ccw(c3054.21,2208.88) 3054.21,2192.5 3066.51,2192.5 3073.01,2199 3091.01,2199 3097.51,2192.5 3115.51,2192.5 3122.01,2199 3140.01,2199 3146.51,2192.5 3164.51,2192.5 3171.01,2199 3189.01,2199 3195.51,2192.5 3213.51,2192.5 3220.01,2199 3238.01,2199 3244.51,2192.5 3262.51,2192.5 3269.01,2199 3287.01,2199 3293.51,2192.5 3311.51,2192.5 3318.01,2199 3336.01,2199 3342.51,2192.5 3447.79,2192.5 ccw(c3447.79,2212.71) 3462.08,2198.42 ccw(c3447.79,2212.71) 3468,2212.71 3468,2448.75 ccw(c3459,2448.75) 3459,2457.75 3396.5,2457.75 cw(c3396.5,2476.25) 3396.5,2494.75 3459,2494.75 ccw(c3459,2503.75) 3468,2503.75 3468,2534 ccw(c3459,2534) 3459,2543 3416.5,2543 cw(c3416.5,2561.5) 3416.5,2580 3456,2580 ccw(c3456,2589) 3465,2589 3465,2615.16 ccw(c3453.66,2615.16) 3453.66,2626.5 3395.75,2626.5 cw(c3395.75,2645) 3377.25,2645 3377.25,2648.86 cw(c3396.39,2648.86) 3396.39,2668 3440.37,2668 ccw(c3440.37,2680.25) 3440.37,2692.5 3413.75,2692.5 cw(c3413.75,2711) 3395.25,2711 3395.25,2734 ccw(c3382.12,2734) 3391.4,2743.29 C140.1@3380,2754.69
HDMI_TX0_SBDP: C139.1 J4.45 | length 1558.7
  TOP w4.5: J4.45@3025.21,2286.88 3025.21,2263.82 3028.33,2260.7 3028.33,2208.88 ccw(c3054.21,2208.88) 3054.21,2183 3447.79,2183 ccw(c3447.79,2212.71) 3468.8,2191.7 ccw(c3447.79,2212.71) 3477.5,2212.71 3477.5,2448.75 ccw(c3459,2448.75) 3459,2467.25 3396.5,2467.25 cw(c3396.5,2476.25) 3396.5,2485.25 3459,2485.25 ccw(c3459,2503.75) 3477.5,2503.75 3477.5,2534 ccw(c3459,2534) 3459,2552.5 3416.5,2552.5 cw(c3416.5,2561.5) 3416.5,2570.5 3456,2570.5 ccw(c3456,2589) 3474.5,2589 3474.5,2615.16 ccw(c3453.66,2615.16) 3453.66,2636 3395.75,2636 cw(c3395.75,2645) 3386.75,2645 3386.75,2648.86 cw(c3396.39,2648.86) 3396.39,2658.5 3440.37,2658.5 ccw(c3440.37,2680.25) 3440.37,2702 3413.75,2702 cw(c3413.75,2711) 3404.75,2711 3404.75,2734 cw(c3417.88,2734) 3408.6,2743.29 C139.1@3420,2754.69
HDMI_TX0_SCL_M0: J3.56 Q6.2 R151.2 | length 1720.9
  TOP w6: J3.56@2097.35,2420.74 2097.35,2344.22 2118.57,2323 2527,2323 v1(2580,2376) ; v1(3349.68,2515.68) R151.2@3349.68,2545 3367.5,2562.82 Q6.2@3367.5,2596.5
  ART03 w6: v1(2580,2376) 2639,2376 2780,2235 2963.24,2235 3016.24,2288 3204,2288 3214,2298 3214,2466 3238,2490 3324,2490 v1(3349.68,2515.68)
HDMI_TX0_SCL_PORT: D29.2 J16.15 Q6.3 R152.2 | length 581.2
  TOP w6: Q6.3@3330,2676.5 3298.5,2676.5 3289.68,2685.32 R152.2@3289.68,2735 3330,2735 v1(3340,2745)
  BOTTOM w6: v1(3340,2745) 3320,2765 3320,2818.56 3326,2824.56 D29.2@3340,2824.56 3340,2845.2 3357.72,2862.92 3357.72,2904.65 3332.57,2929.8 3332.57,3100.01 J16.15@3357.72,3125.16
HDMI_TX0_SDA_M0: C142.2 J3.58 Q7.2 R154.2 | length 1906.1
  TOP w6: J3.58@2113.09,2420.74 2113.09,2350.75 2125.09,2338.75 2503.38,2338.75 v1(2540.63,2376)
  ART03 w6: v1(2540.63,2376) 2573.63,2409 2685,2409 2697,2397 2697,2342 2761.5,2277.5 2972,2277.5 3005.5,2311 3026,2311 3052.51,2337.51 3163,2337.51 3181.94,2356.45 3181.94,2493.94 3228,2540 3419.37,2540 v1(3439.37,2520)
  BOTTOM w6: v1(3439.37,2520) 3446.87,2527.5 Q7.2@3533.5,2527.5 3551.32,2545.32 C142.2@3580,2545.32 3580.32,2545 R154.2@3620.32,2545
HDMI_TX0_SDA_PORT: D28.2 J16.16 Q7.3 R155.2 | length 640.7
  BOTTOM w6: J16.16@3397.09,3102.49 3422.23,3077.34 3422.23,3041.6 3405,3024.37 3405,2949.37 3445,2909.37 3445,2865 3430,2850 D28.2@3430,2824.56 3415.56,2824.56 3407,2816 3407,2698 3400,2691 R155.2@3400,2584.68 3419.68,2565 Q7.3@3453.5,2565
HDMI_TX1_CEC_M0: J1.59 Q23.2 R191.2 | length 4141.4
  TOP w6: J1.59@2128.84,569.96 2128.84,1166.5 2140.84,1178.5 2635,1178.5 2647,1190.5 2647,1506 2659,1518 2993,1518 3005,1530 3005,1764.37 v1(2985,1784.37)
  ART03 w6: v1(2985,1784.37) 3004.37,1765 3044,1765 3089,1810 v1(4351,1810)
  ART04 w6: v1(4351,1810) 4400,1859 v1(4400,2374.37)
  BOTTOM w6: Q23.2@4343.5,2391.87 4372.18,2391.87 R191.2@4390,2409.69 4400,2399.69 v1(4400,2374.37)
HDMI_TX1_CEC_PORT: D38.2 J17.13 Q23.3 R354.2 | length 1362
  ART04 w6: v1(4075,2638.37) 4075,2441.97 4087.6,2429.37 v1(4305,2429.37)
  BOTTOM w6: J17.13@3782.91,3170.64 3735,3122.72 3735,2925 3770.83,2889.17 D38.2@3770.83,2855 3800.83,2825 3845,2825 3855,2815 3855,2673.37 3890,2638.37 v1(4075,2638.37) ; R354.2@4210,2449.05 4229.68,2429.37 Q23.3@4263.5,2429.37 v1(4305,2429.37)
HDMI_TX1_D0N: C148.1 J4.13 | length 2731.3
  TOP w4.5: J4.13@2773.24,2286.88 2773.24,2263.82 2770.11,2260.7 2770.11,1993.76 ccw(c2839.81,1993.76) 2790.53,1944.47 2801.03,1933.97 ccw(c2839.58,1972.52) 2839.58,1918 2880.06,1918 2886.06,1924 2904.06,1924 2910.06,1918 2928.06,1918 2934.06,1924 2952.06,1924 2958.06,1918 2976.06,1918 2982.06,1924 3000.06,1924 3006.06,1918 3024.06,1918 3030.06,1924 3048.06,1924 3054.06,1918 3072.06,1918 3078.06,1924 3096.06,1924 3102.06,1918 3120.06,1918 3126.06,1924 3144.06,1924 3150.06,1918 3622.51,1918 ccw(c3622.51,2002.63) 3682.35,1942.79 3805.51,2065.95 cw(c3872.03,1999.43) 3872.03,2093.5 3954.19,2093.5 ccw(c3954.19,2160.79) 4001.77,2113.21 4082.22,2193.65 ccw(c4023.59,2252.28) 4106.5,2252.28 4106.5,2345.08 ccw(c4097.5,2345.08) 4097.5,2354.08 4082.5,2354.08 cw(c4082.5,2372.58) 4082.5,2391.08 4097.5,2391.08 ccw(c4097.5,2400.08) 4097.5,2409.08 4082.5,2409.08 cw(c4082.5,2427.58) 4082.5,2446.08 4097.5,2446.08 ccw(c4097.5,2455.08) 4097.5,2464.08 4082.5,2464.08 cw(c4082.5,2482.58) 4082.5,2501.08 4097.5,2501.08 ccw(c4097.5,2510.08) 4097.5,2519.08 4082.5,2519.08 cw(c4082.5,2537.58) 4082.5,2556.08 4097.5,2556.08 ccw(c4097.5,2565.08) 4097.5,2574.08 4082.5,2574.08 cw(c4082.5,2592.58) 4082.5,2611.08 4097.5,2611.08 ccw(c4097.5,2620.08) 4106.5,2620.08 4106.5,2650.35 ccw(c4090.35,2650.35) 4090.35,2666.5 4043.91,2666.5 cw(c4043.91,2688.16) 4022.25,2688.16 4022.25,2735 ccw(c4011.53,2735) 4019.11,2742.58 C148.1@4007,2754.69
HDMI_TX1_D0N_PORT: C148.2 D68.2 J17.9 R188.1 | length 701.8
  TOP w4.5: J17.9@3782.91,3261.59 3799.68,3261.59 3800.03,3261.94 3823.75,3261.94 ccw(c3823.75,3284.44) 3839.66,3268.53 3845.18,3274.05 cw(c3859.24,3259.99) 3859.24,3279.87 3868.74,3279.87 cw(c3868.74,3274.43) 3874.17,3274.43 ccw(c3879.61,3274.43) 3879.61,3269 3886.74,3269 ccw(c3886.74,3274.43) 3892.17,3274.43 cw(c3897.61,3274.43) 3897.61,3279.87 3919,3279.87 cw(c3919,3223.33) 3958.97,3263.31 4010.1,3212.18 cw(c3980.78,3182.86) 4022.25,3182.86 4022.25,2853.33 cw(c4012.38,2853.33) 4019.36,2846.35 4018.72,2845.71 ccw(c4025.7,2838.73) 4015.83,2838.73 D68.2@4015.83,2830 4019.23,2826.6 cw(c4012.55,2819.92) 4022,2819.92 4022,2815.99 cw(c4005.24,2815.99) 4017.09,2804.14 v1(4007,2794.05)
HDMI_TX1_D0P: C147.1 J4.11 | length 2731.3
  TOP w4.5: J4.11@2757.49,2286.88 2757.49,2263.82 2760.61,2260.7 2760.61,1993.76 ccw(c2839.81,1993.76) 2783.81,1937.75 2794.31,1927.25 ccw(c2839.58,1972.52) 2839.58,1908.5 3622.51,1908.5 ccw(c3622.51,2002.63) 3689.07,1936.07 3812.23,2059.23 cw(c3872.03,1999.43) 3872.03,2084 3954.19,2084 ccw(c3954.19,2160.79) 4008.49,2106.49 4088.93,2186.93 ccw(c4023.59,2252.28) 4116,2252.28 4116,2345.08 ccw(c4097.5,2345.08) 4097.5,2363.58 4082.5,2363.58 cw(c4082.5,2372.58) 4082.5,2381.58 4097.5,2381.58 ccw(c4097.5,2400.08) 4097.5,2418.58 4082.5,2418.58 cw(c4082.5,2427.58) 4082.5,2436.58 4097.5,2436.58 ccw(c4097.5,2455.08) 4097.5,2473.58 4082.5,2473.58 cw(c4082.5,2482.58) 4082.5,2491.58 4097.5,2491.58 ccw(c4097.5,2510.08) 4097.5,2528.58 4082.5,2528.58 cw(c4082.5,2537.58) 4082.5,2546.58 4097.5,2546.58 ccw(c4097.5,2565.08) 4097.5,2583.58 4082.5,2583.58 cw(c4082.5,2592.58) 4082.5,2601.58 4097.5,2601.58 ccw(c4097.5,2620.08) 4116,2620.08 4116,2650.35 ccw(c4090.35,2650.35) 4090.35,2676 4043.91,2676 cw(c4043.91,2688.16) 4031.75,2688.16 4031.75,2735 cw(c4042.47,2735) 4034.89,2742.58 C147.1@4047,2754.69
HDMI_TX1_D0P_PORT: C147.2 D69.2 J17.7 R189.1 | length 704.4
  TOP w4.5: J17.7@3782.91,3307.05 3799.68,3307.05 3799.76,3307.13 3823.92,3307.13 cw(c3823.92,3284.63) 3839.83,3300.54 3844.41,3295.96 ccw(c3860.32,3311.87) 3860.32,3289.37 3919,3289.37 cw(c3919,3223.33) 3965.69,3270.03 4016.82,3218.9 cw(c3980.78,3182.86) 4031.75,3182.86 4031.75,2853.33 ccw(c4041.62,2853.33) 4034.64,2846.35 4035.28,2845.71 cw(c4028.3,2838.73) 4038.17,2838.73 D69.2@4038.17,2830 4034.52,2826.35 ccw(c4041.8,2819.06) 4031.5,2819.06 4031.5,2815.99 ccw(c4047.05,2815.99) 4036.05,2805 v1(4047,2794.05)
HDMI_TX1_D1N: C146.1 J4.9 | length 2627.9
  TOP w4.5: J4.9@2741.74,2286.88 2741.74,2263.82 2738.62,2260.7 2738.62,1966.91 ccw(c2831.63,1966.91) 2765.86,1901.14 ccw(c2802.41,1937.68) 2802.41,1886 2877.14,1886 2883.14,1892 2901.14,1892 2907.14,1886 2925.14,1886 2931.14,1892 2949.14,1892 2955.14,1886 2973.14,1886 2979.14,1892 2997.14,1892 3003.14,1886 3021.14,1886 3027.14,1892 3045.14,1892 3051.14,1886 3069.14,1886 3075.14,1892 3093.14,1892 3099.14,1886 3117.14,1886 3122.14,1891 3142.14,1891 3147.14,1886 3156.64,1886 3161.64,1891 3185.64,1891 3190.64,1886 3625,1886 ccw(c3625,2006.71) 3710.36,1921.36 3819.64,2030.64 cw(c3888.1,1962.18) 3888.1,2059 3974.38,2059 ccw(c3974.38,2118.44) 4016.41,2076.41 4114.93,2174.93 ; C146.1@4095,2754.69 4106.27,2743.42 cw(c4099.06,2736.22) 4109.25,2736.22 4109.25,2721.24 ccw(c4150.12,2721.24) 4121.22,2692.34 4129.28,2684.28 cw(c4107.03,2662.03) 4138.5,2662.03 4138.5,2541.07 ccw(c4157,2541.07) 4157,2522.57 4158.5,2522.57 cw(c4158.5,2513.57) 4167.5,2513.57 4167.5,2511.85 cw(c4160.22,2511.85) 4160.22,2504.57 4157,2504.57 ccw(c4157,2486.07) 4157,2467.57 4158.5,2467.57 cw(c4158.5,2458.57) 4167.5,2458.57 4167.5,2458.34 cw(c4158.73,2458.34) 4158.73,2449.57 4157,2449.57 ccw(c4157,2431.07) 4157,2412.57 4158.5,2412.57 cw(c4158.5,2403.57) 4167.5,2403.57 cw(c4158.52,2403.54) 4158.52,2394.57 4157,2394.57 ccw(c4157,2376.07) 4157,2357.57 4158.5,2357.57 cw(c4158.5,2348.57) 4167.5,2348.57 4167.5,2347.02 cw(c4160.05,2347.02) 4160.05,2339.57 4157,2339.57 ccw(c4157,2321.07) 4138.5,2321.07 4138.5,2231.84 cw(c4058.01,2231.84) 4114.92,2174.93
HDMI_TX1_D1N_PORT: C146.2 D70.2 J17.6 R186.1 | length 785.4
  TOP w4.5: J17.6@3822.28,3330.05 3833.7,3341.46 cw(c3849.61,3325.55) 3849.61,3348.05 3868.3,3348.05 cw(c3868.3,3335.05) 3877.49,3344.24 3886.77,3334.96 ccw(c3902.68,3350.87) 3902.68,3328.37 3951.61,3328.37 cw(c3951.61,3315.37) 3960.81,3324.56 4091.06,3194.31 4091.06,3181.94 4103.79,3169.21 4116.16,3169.21 4123.23,3162.14 cw(c4091.8,3130.71) 4136.25,3130.71 4136.25,3121.21 4130,3114.96 4130,3092.96 4136.25,3086.71 4136.25,2943.07 cw(c4123.25,2943.07) 4132.44,2933.88 4117.34,2918.78 ccw(c4133.25,2902.87) 4110.75,2902.87 4110.75,2854.19 cw(c4100.02,2854.19) 4107.61,2846.6 4106.97,2845.96 ccw(c4114.56,2838.38) 4103.83,2838.38 D70.2@4103.83,2830 4107.48,2826.35 cw(c4100.2,2819.06) 4110.5,2819.06 4110.5,2815.99 cw(c4094.95,2815.99) 4105.95,2805 v1(4095,2794.05)
HDMI_TX1_D1P: C145.1 J4.7 | length 2625.6
  TOP w4.5: J4.7@2725.99,2286.88 2725.99,2263.82 2729.12,2260.7 2729.12,1966.91 ccw(c2831.63,1966.91) 2759.14,1894.42 ccw(c2802.41,1937.68) 2802.41,1876.5 3625,1876.5 ccw(c3625,2006.71) 3717.07,1914.64 3826.36,2023.92 cw(c3888.1,1962.18) 3888.1,2049.5 3974.38,2049.5 ccw(c3974.38,2118.44) 4023.13,2069.69 4121.64,2168.21 ccw(c4058.01,2231.84) 4148,2231.84 4148,2321.07 cw(c4157,2321.07) 4157,2330.07 4160.05,2330.07 ccw(c4160.05,2347.02) 4177,2347.02 4177,2348.57 ccw(c4158.5,2348.57) 4158.5,2367.07 4157,2367.07 cw(c4157,2376.07) 4157,2385.07 4158.52,2385.07 ccw(c4158.52,2403.54) 4177,2403.54 ccw(c4158.5,2403.57) 4158.5,2422.07 4157,2422.07 cw(c4157,2431.07) 4157,2440.07 4158.73,2440.07 ccw(c4158.73,2458.34) 4177,2458.34 4177,2458.57 ccw(c4158.5,2458.57) 4158.5,2477.07 4157,2477.07 cw(c4157,2486.07) 4157,2495.07 4160.22,2495.07 ccw(c4160.22,2511.85) 4177,2511.85 4177,2513.57 ccw(c4158.5,2513.57) 4158.5,2532.07 4157,2532.07 cw(c4157,2541.07) 4148,2541.07 4148,2662.03 ccw(c4107.03,2662.03) 4136,2691 4127.94,2699.06 cw(c4150.12,2721.24) 4118.75,2721.24 4118.75,2735.22 cw(c4126.52,2735.22) 4121.03,2740.72 C145.1@4135,2754.69
HDMI_TX1_D1P_PORT: C145.2 D71.2 J17.4 R187.1 | length 787.9
  TOP w4.5: J17.4@3822.28,3375.55 3833.7,3364.14 ccw(c3849.61,3380.05) 3849.61,3357.55 3868.3,3357.55 cw(c3868.3,3335.05) 3884.21,3350.96 3893.49,3341.68 ccw(c3902.68,3350.87) 3902.68,3337.87 3951.62,3337.87 cw(c3951.61,3315.37) 3967.53,3331.28 4129.95,3168.86 cw(c4091.8,3130.71) 4145.75,3130.71 4145.75,2943.07 cw(c4123.25,2943.07) 4139.16,2927.16 4124.06,2912.06 ccw(c4133.25,2902.87) 4120.25,2902.87 4120.25,2854.19 ccw(c4130.98,2854.19) 4123.39,2846.6 4124.03,2845.96 cw(c4116.44,2838.38) 4127.17,2838.38 D71.2@4127.17,2830 4123.27,2826.1 ccw(c4131.15,2818.21) 4120,2818.21 4120,2815.49 ccw(c4135.55,2815.49) 4124.55,2804.5 v1(4135,2794.05)
HDMI_TX1_D2N: C144.1 J4.5 | length 2611.6
  TOP w4.5: J4.5@2710.25,2286.88 2710.25,2263.82 2707.12,2260.7 2707.12,1927.93 ccw(c2784.05,1927.93) 2784.05,1851 2880.61,1851 2886.61,1857 2904.61,1857 2910.61,1851 2928.61,1851 2934.61,1857 2952.61,1857 2958.61,1851 2976.61,1851 2982.61,1857 3000.61,1857 3006.61,1851 3024.61,1851 3030.61,1857 3048.61,1857 3054.61,1851 3072.61,1851 3080.61,1859 3094.61,1859 3102.61,1851 3634.26,1851 ccw(c3634.26,1984.52) 3728.67,1890.11 3826.35,1987.78 cw(c3904.13,1910) 3904.13,2020 3993.16,2020 ccw(c3993.16,2089.63) 4042.39,2040.39 4170.48,2168.48 ccw(c4101.04,2237.93) 4199.25,2237.93 4199.25,2733 ccw(c4183.7,2733) 4194.7,2743.99 C144.1@4184,2754.69
HDMI_TX1_D2N_PORT: C144.2 D72.2 J17.3 R184.1 | length 897.8
  TOP w4.5: J17.3@3782.91,3398 3799.68,3398 3799.84,3398.15 3822,3398.15 ccw(c3821.99,3420.66) 3837.91,3404.74 3843.66,3410.5 cw(c3856.55,3397.61) 3856.55,3415.84 3860.59,3415.84 cw(c3860.59,3405.19) 3868.12,3412.72 3884.88,3395.96 ccw(c3931.11,3442.19) 3931.11,3376.81 3951.56,3376.81 cw(c3951.56,3355.08) 3966.93,3370.44 4154.45,3182.92 cw(c4105.77,3134.24) 4174.61,3134.24 4174.61,3040.27 4165,3030.66 4165,3014.66 4174.61,3005.04 4174.61,2987.04 4166,2978.43 4166,2960.43 4174.61,2951.82 4174.61,2938.27 ccw(c4197.11,2938.27) 4181.2,2922.36 4196.44,2907.12 cw(c4187.25,2897.93) 4200.25,2897.93 4200.25,2853.33 cw(c4190.38,2853.33) 4197.36,2846.35 4196.72,2845.71 ccw(c4203.7,2838.73) 4193.83,2838.73 D72.2@4193.83,2830 4197.23,2826.6 cw(c4190.55,2819.92) 4200,2819.92 4200,2816.49 cw(c4184.45,2816.49) 4195.45,2805.5 v1(4184,2794.05)
HDMI_TX1_D2P: C143.1 J4.3 | length 2614.9
  TOP w4.5: J4.3@2694.5,2286.88 2694.5,2263.82 2697.62,2260.7 2697.62,1927.93 ccw(c2784.05,1927.93) 2784.05,1841.5 3634.26,1841.5 ccw(c3634.26,1984.52) 3735.39,1883.39 3833.07,1981.06 cw(c3904.13,1910) 3904.13,2010.5 3993.16,2010.5 ccw(c3993.16,2089.63) 4049.11,2033.67 ; 4049.11,2033.67 4177.2,2161.77 ccw(c4101.04,2237.93) 4208.75,2237.93 4208.75,2733 cw(c4224.3,2733) 4213.3,2743.99 C143.1@4224,2754.69
HDMI_TX1_D2P_PORT: C143.2 D73.2 J17.1 R185.1 | length 897.3
  TOP w4.5: J17.1@3782.91,3443.47 3783.12,3443.68 3822.32,3443.68 cw(c3822.32,3421.18) 3838.23,3437.09 3843.6,3431.72 ccw(c3859.01,3447.13) 3859.01,3425.34 3860.59,3425.34 cw(c3860.59,3405.19) 3874.84,3419.44 3891.6,3402.67 ccw(c3931.11,3442.19) 3931.11,3386.31 3951.57,3386.31 cw(c3951.56,3355.08) 3973.65,3377.16 4161.17,3189.64 cw(c4105.77,3134.24) 4184.11,3134.24 4184.11,2938.27 ccw(c4197.11,2938.27) 4187.92,2929.08 4203.16,2913.84 cw(c4187.25,2897.93) 4209.75,2897.93 4209.75,2853.33 ccw(c4219.62,2853.33) 4212.64,2846.35 4213.28,2845.71 cw(c4206.3,2838.73) 4216.17,2838.73 D73.2@4216.17,2830 4212.52,2826.35 ccw(c4219.8,2819.06) 4209.5,2819.06 4209.5,2815.49 ccw(c4226.26,2815.49) 4214.41,2803.64 v1(4224,2794.05)
HDMI_TX1_D3N: C150.1 J4.17 | length 2830.9
  TOP w4.5: J4.17@2804.73,2286.88 2804.73,2263.82 2801.61,2260.7 2801.61,2015.33 ccw(c2872.84,2015.33) 2822.47,1964.96 ccw(c2854.97,1997.45) 2854.97,1951.5 2882.31,1951.5 2889.81,1959 2907.81,1959 2915.31,1951.5 2933.31,1951.5 2940.81,1959 2958.81,1959 2966.31,1951.5 2984.31,1951.5 2991.81,1959 3009.81,1959 3017.31,1951.5 3035.31,1951.5 3042.81,1959 3060.81,1959 3068.31,1951.5 3086.31,1951.5 3093.81,1959 3111.81,1959 3119.31,1951.5 3604.77,1951.5 ccw(c3604.77,2027.04) 3658.19,1973.63 3815.64,2131.08 cw(c3828.73,2118) 3828.73,2136.5 3838.7,2136.5 ccw(c3838.7,2145.5) 3847.7,2145.5 3847.7,2153.25 cw(c3864.45,2153.25) 3864.45,2170 3866.2,2170 cw(c3866.2,2151.5) 3884.7,2151.5 3884.7,2135.5 ccw(c3893.7,2135.5) 3902.7,2135.5 3902.7,2153.25 cw(c3919.45,2153.25) 3919.45,2170 3921.2,2170 cw(c3921.2,2151.5) 3939.7,2151.5 3939.7,2145.5 ccw(c3948.7,2145.5) 3948.7,2136.5 3958.2,2136.5 ccw(c3958.2,2174.79) 3985.28,2147.72 4023.97,2186.41 ccw(c3994.93,2215.45) 4036,2215.45 4036,2223.68 cw(c4053.74,2223.68) 4053.73,2241.41 4062.5,2241.41 ccw(c4062.5,2250.41) 4062.5,2259.41 4049.5,2259.41 cw(c4049.5,2277.91) 4049.5,2296.41 4063.25,2296.41 ccw(c4063.25,2304.66) 4071.5,2304.66 4071.5,2305.41 ccw(c4062.5,2305.41) 4062.5,2314.41 4054.5,2314.41 cw(c4054.5,2332.91) 4036,2332.91 4036,2503.17 ccw(c4019.67,2503.17) 4019.67,2519.5 3946.08,2519.5 cw(c3946.08,2539.08) 3926.5,2539.08 3926.5,2544 cw(c3945,2544) 3945,2562.5 4021.16,2562.5 ccw(c4021.16,2575.87) 4021.16,2589.24 3950.75,2589.24 cw(c3950.75,2612.49) 3927.5,2612.49 cw(c3950.75,2612.49) 3950.75,2635.74 3986.5,2635.74 ccw(c3986.5,2644.74) 3986.5,2653.74 3952.75,2653.74 cw(c3952.75,2672.24) 3934.25,2672.24 3934.25,2734.22 ccw(c3921.65,2734.22) 3930.56,2743.13 C150.1@3919,2754.69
